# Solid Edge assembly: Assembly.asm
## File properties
Author: Administrator
Template: Normal.asm
Last saved by: CADCIM
Revision: 23
Application: Solid Edge
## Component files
Stock_support_base.par
thrust_bearing.par
adjusting_screw_nut.par
support_adjusting_screw.par
support_roller_bracket.par
stock_support_roller.par
adjusting_nut_handle.par
adjusting_screw_guide.par
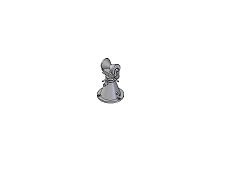
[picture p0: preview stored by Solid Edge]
